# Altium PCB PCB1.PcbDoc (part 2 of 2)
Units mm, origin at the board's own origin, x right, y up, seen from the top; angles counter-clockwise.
Board outline 98.6 x 67.31 mm, 4 copper layers (Top Layer, GND, PWR, Bottom Layer), stack 1.57 mm thick; 89 components, 101 nets, 372 pads, 350 vias.
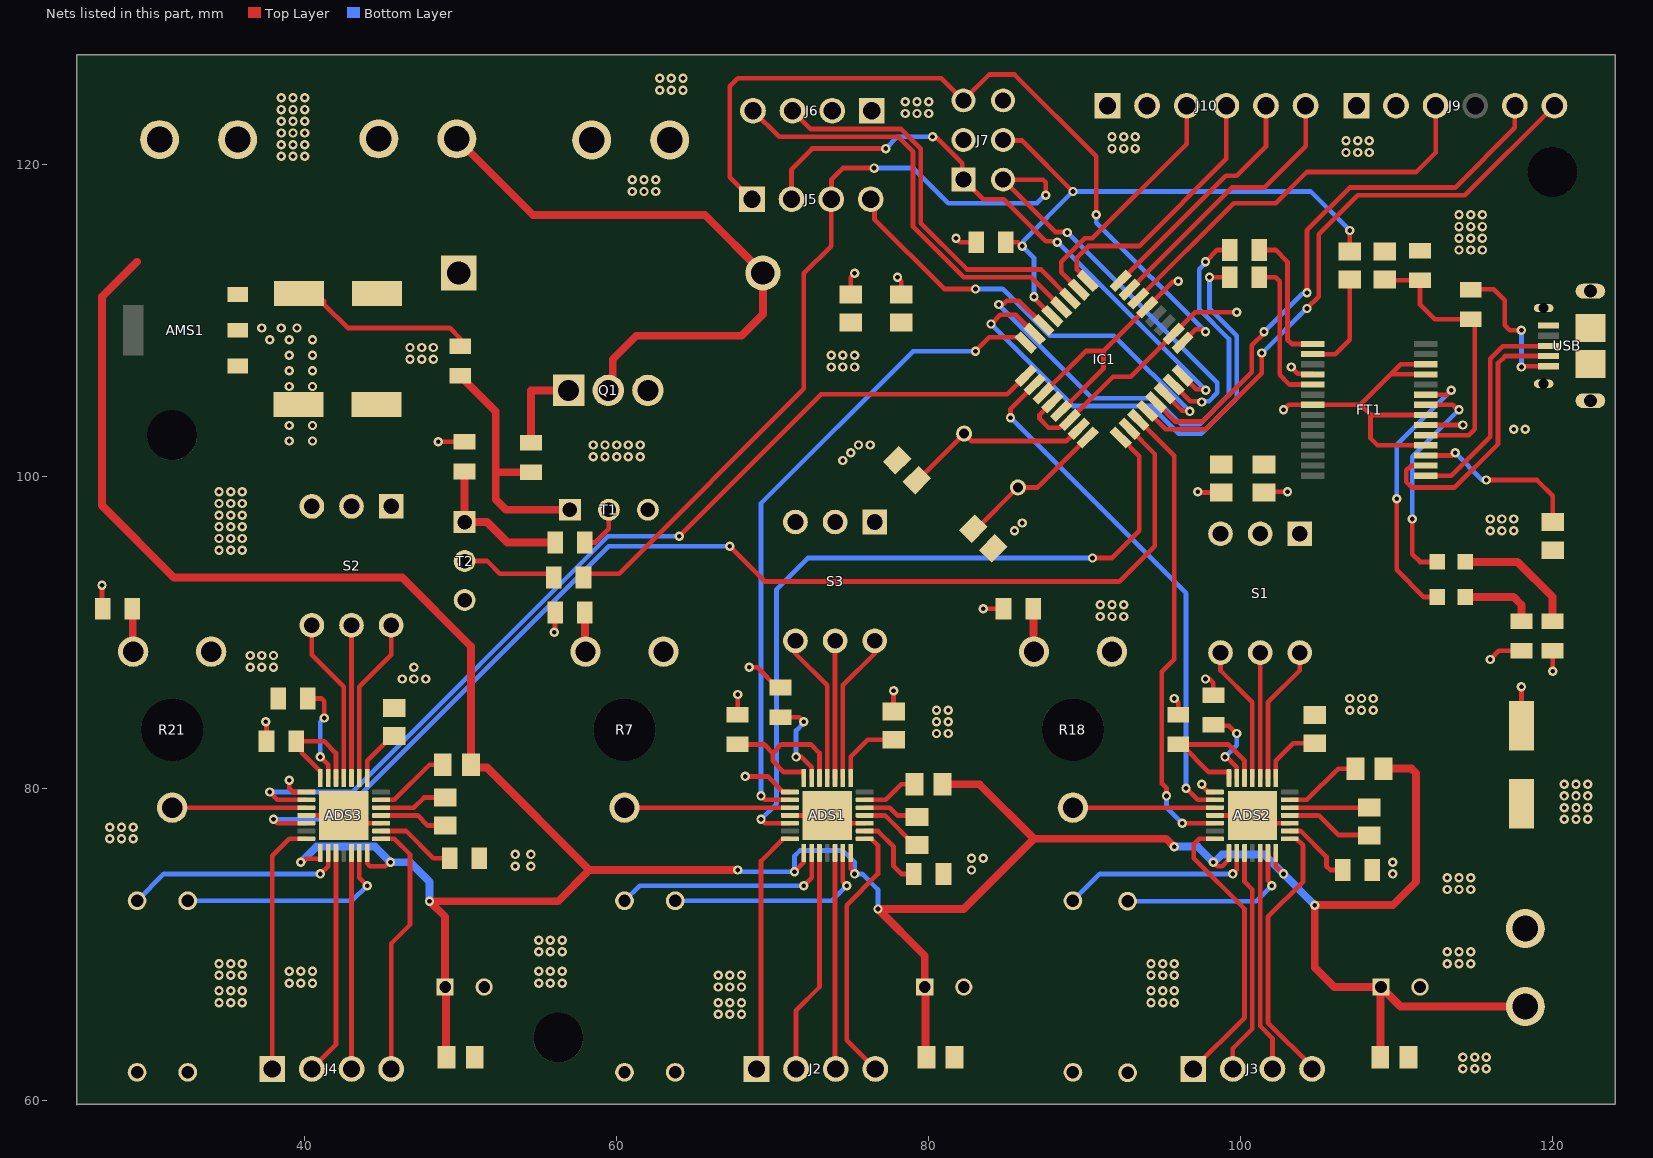
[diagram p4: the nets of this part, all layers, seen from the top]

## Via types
v1: diameter 0.6, hole 0.3, Top Layer to Bottom Layer, 350 vias

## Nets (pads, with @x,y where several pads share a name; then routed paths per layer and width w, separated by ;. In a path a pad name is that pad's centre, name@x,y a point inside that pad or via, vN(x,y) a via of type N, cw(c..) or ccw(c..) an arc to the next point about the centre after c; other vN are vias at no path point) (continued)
ADC7: IC1.22 J9.3 | length 25.9
  Top Layer w0.3: IC1.22@93.442,111.389 99.553,117.5 102.25,117.5 104.25,119.5 111.25,119.5 112.5,120.75 J9.3@112.5,123.75
AT.MOSI: IC1.15 J5.3 J7.4 R31.1 | length 75.6
  Top Layer w0.3: R31.1@57.75,93.25 58.25,93.75 60.15,93.75 72,105.6 72,113 73.75,114.75 J5.3@73.75,117.75 73.775,117.775 73.775,119.025 74.5,119.75 v1(76.5,119.75) ; v1(87.5,118) 87.5,118.834 87.324,119.01 J7.4@84.77,119.01 88.125,115.655 88.845,115.655 v1(88.875,115.625) ; IC1.15@95.705,105.874 96.771,104.807 97.443,104.807 v1(97.5,104.75)
  Bottom Layer w0.3: v1(76.5,119.75) 79,119.75 81.25,117.5 86.939,117.5 87.439,118 v1(87.5,118) ; v1(88.875,115.625) 98.5,106 98.5,105.337 97.971,104.807 97.557,104.807 v1(97.5,104.75)
GND: ADS1.3 ADS1.18 ADS1.29 ADS2.3 ADS2.18 ADS2.29 ADS3.3 ADS3.18 ADS3.29 AMS1.1 C3.1 C4.1 C5.1 C6.1 C11.2 C12.2 C13.2 C14.1 C15.1 C16.1 C17.1 C18.2 C19.2 C20.2 C21.2 C22.2 C23.1 C24.1 C25.1 C26.1 FT1.7 FT1.18 FT1.21 FT1.25 FT1.26 IC1.3 IC1.5 IC1.21 J1.1 J6.1 J7.6 J8.2 J9.1 J10.1 J11.2 Q1.3 R2.1 R4.1 R5.1 R6.1 R7.1 R10.1 R11.1 R14.1 R15.1 R16.1 R17.1 R18.1 R19.1 R20.1 R21.1 R28.1 T1.E T2.E USB.5 USB.S1 USB.S2 USB.S3 USB.S4 USB.S5 USB.S6 | length 59.2
  Top Layer w0.3: ADS3.18@40.1,78.25 42.25,78.25 42.75,77.75 ADS3.3@44.9,77.75 ; v1(68.5,87.75) 69,87.75 70.3,86.45 R2.1@70.5,86.45 ; ADS1.18@71.1,78.25 73.25,78.25 73.75,77.75 ADS1.3@75.9,77.75 ; C6.1@77.75,84.9 v1(77.75,86.25) ; IC1.3@87.361,105.308 90.074,108.021 91.206,108.021 ; IC1.5@88.492,104.177 91.206,106.89 91.206,108.021 ; v1(96,112.5) 95.684,112.5 IC1.21@94.008,110.823 91.206,108.021 ; v1(97.75,87) 98,87 98.25,86.75 R10.1@98.25,85.95 ; ADS2.18@98.35,78.25 ADS2.29@100.75,78.25 101.25,77.75 ADS2.3@103.15,77.75 ; v1(102.75,104.25) 103.075,104.575 FT1.7@104.625,104.575 107.675,104.575 ; FT1.18@111.875,101.975 108.775,101.975 108.325,102.425 108.325,103.925 ; FT1.21@111.875,103.925 108.325,103.925 ; FT1.25@111.875,106.525 109.625,106.525 ; FT1.26@111.875,107.175 110.275,107.175 109.625,106.525 ; 107.675,104.575 108.325,103.925 ; 107.675,104.575 109.625,106.525
  other v1: 114.25,62 115,62 115.75,62 114.25,62.75 115,62.75 115.75,62.75 66.5,65.5 67.25,65.5 68,65.5 34.5,66.25 35.25,66.25 36,66.25 66.5,66.25 67.25,66.25 68,66.25 94.25,66.25 95,66.25 95.75,66.25 34.5,67 35.25,67 36,67 94.25,67 95,67 95.75,67 66.5,67.25 67.25,67.25 68,67.25 39,67.5 39.75,67.5 40.5,67.5 55,67.5 55.75,67.5 56.5,67.5 34.5,68 35.25,68 36,68 66.5,68 67.25,68 68,68 94.25,68 95,68 95.75,68 39,68.25 39.75,68.25 40.5,68.25 55,68.25 55.75,68.25 56.5,68.25 34.5,68.75 35.25,68.75 36,68.75 94.25,68.75 95,68.75 95.75,68.75 113.25,68.75 114,68.75 114.75,68.75 55,69.5 55.75,69.5 56.5,69.5 113.25,69.5 114,69.5 114.75,69.5 55,70.25 55.75,70.25 56.5,70.25 113.25,73.5 114,73.5 114.75,73.5 113.25,74.25 114,74.25 114.75,74.25 109.75,74.5 82.75,74.75 53.5,75 54.5,75 109.75,75.25 82.75,75.5 83.5,75.5 53.5,75.75 54.5,75.75 27.5,76.75 28.25,76.75 29,76.75 27.5,77.5 28.25,77.5 29,77.5 120.75,78 121.5,78 122.25,78 120.75,78.75 121.5,78.75 122.25,78.75 120.75,79.5 121.5,79.5 122.25,79.5 120.75,80.25 121.5,80.25 122.25,80.25 80.5,83.5 81.25,83.5 80.5,84.25 81.25,84.25 80.5,85 81.25,85 107,85 107.75,85 108.5,85 107,85.75 107.75,85.75 108.5,85.75 46.25,87 47,87 47.75,87 36.5,87.75 37.25,87.75 38,87.75 47,87.75 36.5,88.5 37.25,88.5 38,88.5 91,91 91.75,91 92.5,91 91,91.75 91.75,91.75 92.5,91.75 34.5,95.25 35.25,95.25 36,95.25 34.5,96 35.25,96 36,96 85.5,96.5 116,96.5 116.75,96.5 117.5,96.5 34.5,96.75 35.25,96.75 36,96.75 86,97 116,97.25 116.75,97.25 117.5,97.25 34.5,97.5 35.25,97.5 36,97.5 34.5,98.25 35.25,98.25 36,98.25 34.5,99 35.25,99 36,99 74.5,101 58.5,101.25 59.25,101.25 60,101.25 60.75,101.25 61.5,101.25 75,101.5 58.5,102 59.25,102 60,102 60.75,102 61.5,102 75.5,102 76.25,102 117.5,103 118.25,103 73.75,107 74.5,107 75.25,107 46.75,107.5 47.5,107.5 48.25,107.5 73.75,107.75 74.5,107.75 75.25,107.75 46.75,108.25 47.5,108.25 48.25,108.25 114,114.5 114.75,114.5 115.5,114.5 114,115.25 114.75,115.25 115.5,115.25 114,116 114.75,116 115.5,116 114,116.75 114.75,116.75 115.5,116.75 61,118.25 61.75,118.25 62.5,118.25 61,119 61.75,119 62.5,119 38.5,120.5 39.25,120.5 40,120.5 106.75,120.75 107.5,120.75 108.25,120.75 91.75,121 92.5,121 93.25,121 38.5,121.25 39.25,121.25 40,121.25 106.75,121.5 107.5,121.5 108.25,121.5 91.75,121.75 92.5,121.75 93.25,121.75 38.5,122 39.25,122 40,122 38.5,122.75 39.25,122.75 40,122.75 78.5,123.25 79.25,123.25 80,123.25 38.5,123.5 39.25,123.5 40,123.5 78.5,124 79.25,124 80,124 38.5,124.25 39.25,124.25 40,124.25 62.75,124.75 63.5,124.75 64.25,124.75 62.75,125.5 63.5,125.5 64.25,125.5
MISO: IC1.16 J5.2 J7.1 | length 38.5
  Top Layer w0.3: J5.2@71.21,117.75 71.21,119.685 72.525,121 v1(77.25,121) ; v1(80.25,121.75) 80.307,121.693 80.517,121.693 81.115,121.095 81.115,121.088 81.768,120.435 81.775,120.435 82.161,120.049 82.161,119.079 83.49,117.75 84.819,117.75 87.511,115.057 88.193,115.057 v1(88.25,115) ; IC1.16@96.27,106.439 97.143,105.566 97.696,105.566 v1(97.753,105.509)
  Bottom Layer w0.3: v1(77.25,121) 78,121.75 v1(80.25,121.75) ; v1(88.25,115) 88.262,115 v1(97.753,105.509)
MOT_VCC: D1.1 J8.1 J12.1
MS1: ADS2.9 S1.1B | length 8.9
  Top Layer w0.3: ADS2.9@101.75,80.65 101.75,85.5 103.79,87.54 S1.1B@103.79,88.69
MS2: ADS2.10 S1.2B | length 8
  Top Layer w0.3: ADS2.10@101.25,80.65 S1.2B@101.25,88.69
MS3: ADS2.11 S1.3B | length 8.9
  Top Layer w0.3: S1.3B@98.71,88.69 98.71,87.54 100.75,85.5 ADS2.11@100.75,80.65
MS11: ADS3.9 S2.1B | length 10.6
  Top Layer w0.3: ADS3.9@43.5,80.65 43.5,86.5 45.54,88.54 S2.1B@45.54,90.44
MS22: ADS3.10 S2.2B | length 9.8
  Top Layer w0.3: ADS3.10@43,80.65 43,81.075 S2.2B@43,90.44
MS33: ADS3.11 S2.3B | length 10.6
  Top Layer w0.3: S2.3B@40.46,90.44 40.46,88.54 42.5,86.5 ADS3.11@42.5,80.65
MS111: ADS1.9 S3.1B | length 8.8
  Top Layer w0.3: ADS1.9@74.5,80.65 74.5,86.59 76.54,88.63
MS222: ADS1.10 S3.2B | length 8
  Top Layer w0.3: ADS1.10@74,80.65 74,88.63
MS333: ADS1.11 S3.3B | length 9.6
  Top Layer w0.3: S3.3B@71.46,89.44 71.46,88.63 73.5,86.59 ADS1.11@73.5,80.65
NetADS1_1: ADS1.1 J2.4 | length 16.9
  Top Layer w0.3: ADS1.1@75.9,76.75 76.325,76.75 76.75,76.325 76.75,74.5 74.75,72.5 74.75,63.83 J2.4@76.58,62
NetADS1_2: ADS1.2 R4.2 | length 5
  Top Layer w0.3: ADS1.2@75.9,77.25 76.75,77.25 77.75,76.25 77.75,75 78.25,74.5 R4.2@79.05,74.5
NetADS1_4: ADS1.4 C1.2 | length 4.1
  Top Layer w0.3: ADS1.4@75.9,78.25 77.2,78.25 79.1,76.35 C1.2@79.25,76.35
NetADS1_5: ADS1.5 C1.1 | length 3.6
  Top Layer w0.3: ADS1.5@75.9,78.75 77.5,78.75 78,78.25 79.15,78.25 C1.1@79.25,78.15
NetADS1_6: ADS1.6 C2.1 | length 3.6
  Top Layer w0.3: ADS1.6@75.9,79.25 77.25,79.25 78.25,80.25 C2.1@79.1,80.25
NetADS1_8: ADS1.8 C6.2 | length 4.6
  Top Layer w0.3: ADS1.8@75,80.65 75,82 76.1,83.1 C6.2@77.75,83.1
NetADS1_12: ADS1.12 ADS1.14 R1.1 | length 10.7
  Top Layer w0.3: R1.1@67.75,82.8 69.45,82.8 70,82.25 ; ADS1.14@72,80.65 72,81.03 70.72,81.03 70,81.75 70,82.25 ; ADS1.12@73,80.65 73,82.25 72.45,82.8 70.55,82.8 70,82.25
NetADS1_13: ADS1.13 R2.2 | length 6
  Top Layer w0.3: R2.2@70.5,84.55 71.7,84.55 v1(72,84.25) ; v1(71.5,82) 71.844,82 72.5,81.344 ADS1.13@72.5,80.65
  Bottom Layer w0.3: v1(71.5,82) 71.5,83.689 72,84.189 v1(72,84.25)
NetADS1_17: ADS1.17 R7.3 | length 10.6
  Top Layer w0.3: R7.3@60.5,78.75 ADS1.17@71.1,78.75
NetADS1_21: ADS1.21 J2.1 | length 15.9
  Top Layer w0.3: J2.1@68.96,62 69.25,62.29 69.25,75.325 70.675,76.75 ADS1.21@71.1,76.75
NetADS1_23: ADS1.23 R6.2 | length 14.2
  Top Layer w0.3: v1(72,73.75) 72.5,74.25 ADS1.23@72.5,75.85
  Bottom Layer w0.3: R6.2@60.5,72.778 61.472,73.75 v1(72,73.75)
NetADS1_24: ADS1.24 J2.2 | length 14.5
  Top Layer w0.3: J2.2@71.5,62 71.5,65.75 73,67.25 ADS1.24@73,75.85
NetADS1_26: ADS1.26 J2.3 | length 13.9
  Top Layer w0.3: ADS1.26@74,75.85 74,62.04 J2.3@74.04,62
NetADS1_27: ADS1.27 R5.2 | length 13.6
  Top Layer w0.3: ADS1.27@74.5,75.85 74.5,74 v1(74.75,73.75)
  Bottom Layer w0.3: R5.2@63.75,72.778 73.778,72.778 v1(74.75,73.75)
NetADS2_1: ADS2.1 J3.4 | length 17.5
  Top Layer w0.3: ADS2.1@103.15,76.75 103.575,76.75 104,76.325 104,74 101.75,71.75 101.75,64.957 104.58,62.127 J3.4@104.58,62
NetADS2_2: ADS2.2 R14.2 | length 4.8
  Top Layer w0.3: ADS2.2@103.15,77.25 103.844,77.25 105.5,75.594 105.5,75 105.75,74.75 R14.2@106.55,74.75
NetADS2_4: ADS2.4 C7.2 | length 5.6
  Top Layer w0.3: ADS2.4@103.15,78.25 105,78.25 106.25,77 108.2,77 C7.2@108.25,76.95
NetADS2_5: ADS2.5 C7.1 | length 5.1
  Top Layer w0.3: ADS2.5@103.15,78.75 C7.1@108.25,78.75
NetADS2_6: ADS2.6 C9.1 | length 5
  Top Layer w0.3: ADS2.6@103.15,79.25 104.25,79.25 106.25,81.25 C9.1@107.35,81.25
NetADS2_8: ADS2.8 C14.2 | length 4.1
  Top Layer w0.3: ADS2.8@102.25,80.65 102.25,81.75 103.375,82.875 C14.2@104.75,82.875
NetADS2_12: ADS2.12 ADS2.14 R8.1 | length 9.9
  Top Layer w0.3: R8.1@96,82.8 R8.1@96.2,82.8 ; ADS2.14@99.25,80.65 99.25,81.03 97.97,81.03 R8.1@96.2,82.8 ; ADS2.12@100.25,80.65 100.25,81.75 99.2,82.8 R8.1@96.2,82.8
NetADS2_13: ADS2.13 R10.2 | length 5.3
  Top Layer w0.3: R10.2@98.25,84.05 98.3,84 99.25,84 v1(99.75,83.5) ; v1(99,82) 99.057,81.943 99.151,81.943 99.75,81.344 ADS2.13@99.75,80.65
  Bottom Layer w0.3: v1(99,82) 99.75,82.75 v1(99.75,83.5)
NetADS2_17: ADS2.17 R18.3 | length 9.1
  Top Layer w0.3: R18.3@89.25,78.75 ADS2.17@98.35,78.75
NetADS2_21: ADS2.21 J3.1 | length 18.6
  Top Layer w0.3: J3.1@96.96,62 100.25,65.29 100.25,72.25 97,75.5 97,76.4 97.35,76.75 ADS2.21@98.35,76.75
NetADS2_23: ADS2.23 R17.2 | length 12.4
  Top Layer w0.3: v1(99.5,74.5) 99.75,74.75 ADS2.23@99.75,75.85
  Bottom Layer w0.3: R17.2@89.25,72.778 90.972,74.5 v1(99.5,74.5)
NetADS2_24: ADS2.24 J3.2 | length 14.6
  Top Layer w0.3: J3.2@99.5,62 99.5,63.308 100.75,64.558 100.75,73.5 100.25,74 ADS2.24@100.25,75.85
NetADS2_26: ADS2.26 J3.3 | length 14.2
  Top Layer w0.3: ADS2.26@101.25,75.85 101.25,64.75 102.04,63.96 J3.3@102.04,62
NetADS2_27: ADS2.27 R16.2 | length 11.9
  Top Layer w0.3: ADS2.27@101.75,75.85 101.75,74.081 102,73.831 v1(102,73.75)
  Bottom Layer w0.3: R16.2@92.75,72.75 101,72.75 v1(102,73.75)
NetADS3_1: ADS3.1 J4.4 | length 16.5
  Top Layer w0.3: ADS3.1@44.9,76.75 45.75,76.75 46.75,75.75 46.75,71.25 45.54,70.04 J4.4@45.54,62
NetADS3_2: ADS3.2 R15.2 | length 5.3
  Top Layer w0.3: ADS3.2@44.9,77.25 46.5,77.25 48.25,75.5 R15.2@49.516,75.5
NetADS3_4: ADS3.4 C8.2 | length 4.4
  Top Layer w0.3: ADS3.4@44.9,78.25 47.25,78.25 47.9,77.6 C8.2@49,77.6
NetADS3_5: ADS3.5 C8.1 | length 4.4
  Top Layer w0.3: ADS3.5@44.9,78.75 47,78.75 47.65,79.4 C8.1@49,79.4
NetADS3_6: ADS3.6 C10.1 | length 4.9
  Top Layer w0.3: ADS3.6@44.9,79.25 45.75,79.25 48,81.5 C10.1@48.85,81.5
NetADS3_8: ADS3.8 C15.2 | length 3.5
  Top Layer w0.3: ADS3.8@44,80.65 44,81.75 45.6,83.35 C15.2@45.75,83.35
NetADS3_12: ADS3.12 ADS3.14 R9.1 | length 7.5
  Top Layer w0.3: ADS3.14@41,80.65 41,81.075 39.8,82.275 39.8,82.65 R9.1@39.45,83 41.25,83 42,82.25 ADS3.12@42,80.65
NetADS3_13: ADS3.13 R11.2 | length 6.4
  Top Layer w0.3: R11.2@40.2,85.75 41.074,85.75 41.25,85.574 v1(41.25,84.5) ; v1(41,82) 41.5,81.5 ADS3.13@41.5,80.65
  Bottom Layer w0.3: v1(41,82) 41,84.25 v1(41.25,84.5)
NetADS3_17: ADS3.17 R21.3 | length 8.6
  Top Layer w0.3: R21.3@31.5,78.75 ADS3.17@40.1,78.75
NetADS3_21: ADS3.21 J4.1 | length 16.3
  Top Layer w0.3: J4.1@37.92,62 37.92,75.67 39,76.75 ADS3.21@40.1,76.75
NetADS3_23: ADS3.23 R20.2 | length 14
  Top Layer w0.3: v1(41,74.5) 41.5,75 ADS3.23@41.5,75.85
  Bottom Layer w0.3: R20.2@29.25,72.778 30.972,74.5 v1(41,74.5)
NetADS3_24: ADS3.24 J4.2 | length 14.5
  Top Layer w0.3: J4.2@40.46,62 42,63.54 ADS3.24@42,75.85
NetADS3_26: ADS3.26 J4.3 | length 13.9
  Top Layer w0.3: J4.3@43,62 43,75.425 ADS3.26@43,75.85
NetADS3_27: ADS3.27 R19.2 | length 14.2
  Top Layer w0.3: ADS3.27@43.5,75.85 43.5,74.25 v1(44,73.75)
  Bottom Layer w0.3: R19.2@32.5,72.778 43.028,72.778 v1(44,73.75)
NetC25_2: C25.2 FT1.19 R27.1 R28.2 | length 17.9
  Top Layer w0.3: C25.2@109.25,112.6 109.3,112.55 R28.2@111.5,112.55 111.5,111 112.45,110.05 R27.1@114.75,110.05 115,109.8 115,103 114.625,102.625 FT1.19@111.875,102.625
NetC26_2: C26.2 FT1.17 | length 11
  Top Layer w0.3: FT1.17@111.875,101.325 113.575,101.325 v1(113.75,101.5) ; v1(115.75,99.75) 119,99.75 120,98.75 C26.2@120,97.05
  Bottom Layer w0.3: v1(113.75,101.5) 115.5,99.75 v1(115.75,99.75)
NetC27_1: C27.1 FT1.2 | length 6.6
  Top Layer w0.3: FT1.2@104.625,107.825 106.075,107.825 107,108.75 C27.1@107,112.6
NetD1_2: D1.2 J12.2 Q1.2 | length 38.8
  Top Layer w0.5: J12.2@49.75,121.625 54.625,116.75 65.65,116.75 D1.2@69.375,113.025 69.375,110.375 68,109 61.25,109 59.749,107.499 59.749,105.789 Q1.2@59.46,105.5
NetFT1_15: FT1.15 USB.3 | length 14.3
  Top Layer w0.3: FT1.15@111.875,100.025 113.502,100.025 116,102.523 116,107.516 116.809,108.325 USB.3@119.825,108.325
NetFT1_16: FT1.16 USB.2 | length 18
  Top Layer w0.3: FT1.16@111.875,100.675 110.925,100.675 110.625,100.375 110.625,99.625 110.975,99.275 113.725,99.275 116.5,102.05 116.5,107.25 116.95,107.7 USB.2@119.75,107.7 USB.2@119.825,107.7
NetFT1_22: FT1.22 LED2.1 | length 14.6
  Top Layer w0.3: v1(111,97.25) 111,95 111.5,94.5 LED2.1@112.6,94.5 ; FT1.22@111.875,104.575 113.594,104.575 113.919,104.25 v1(114,104.25)
  Bottom Layer w0.3: v1(111,97.25) 111,101.25 v1(114,104.25)
NetFT1_23: FT1.23 LED1.1 | length 18
  Top Layer w0.3: v1(110,98.552) 110,94 111.75,92.25 LED1.1@112.6,92.25 ; FT1.23@111.875,105.225 113.225,105.225 v1(113.5,105.5)
  Bottom Layer w0.3: v1(110,98.552) 110,102 v1(113.5,105.5)
NetIC1_30: IC1.30 R23.1 | length 33.7
  Top Layer w0.3: v1(84.5,111) 84.557,111.057 84.807,111.057 85,111.25 85.776,111.25 87.334,109.692 IC1.30@87.361,109.692 ; v1(97.75,113.75) 98.5,114.5 R23.1@99.3,114.5
  Bottom Layer w0.3: v1(84.5,111) 90.5,105 94.5,105 96.175,103.325 97.368,103.325 99.25,105.207 99.25,108.793 97.35,110.693 97.35,113.269 97.75,113.669 v1(97.75,113.75)
NetIC1_31: IC1.31 R24.1 | length 32.9
  Top Layer w0.3: v1(84,109.75) 84.6,110.35 85.572,110.35 IC1.31@86.795,109.126 ; v1(98,112.75) R24.1@99.3,112.75
  Bottom Layer w0.3: v1(84,109.75) 89.25,104.5 94.25,104.5 96.025,102.725 97.475,102.725 99.75,105 99.75,109 98,110.75 v1(98,112.75)
NetLED1_2: LED1.2 R25.1 | length 4.9
  Top Layer w0.5: LED1.2@114.4,92.25 117.5,92.25 118,91.75 R25.1@118,90.7
NetLED2_2: LED2.2 R26.1 | length 8.1
  Top Layer w0.5: LED2.2@114.4,94.5 117.75,94.5 120,92.25 R26.1@120,90.7
NetQ1_1: Q1.1 R32.2 | length 5.8
  Top Layer w0.5: R32.2@54.5,102.15 54.5,105.5 Q1.1@56.92,105.5
NetR3_1: R3.1 R7.2 | length 2.8
  Top Layer w0.5: R3.1@57.95,91.5 57.975,91.475 57.975,88.775 R7.2@58,88.75
NetR12_1: R12.1 R18.2 | length 2.8
  Top Layer w0.5: R12.1@86.7,91.5 86.725,91.475 86.725,88.775 R18.2@86.75,88.75
NetR13_1: R13.1 R21.2 | length 2.8
  Top Layer w0.5: R13.1@28.95,91.5 28.975,91.475 28.975,88.775 R21.2@29,88.75
NetR27_2: R27.2 USB.1 | length 9.5
  Top Layer w0.3: R27.2@114.75,111.95 114.775,111.975 116.23,111.975 116.925,111.28 116.925,109.675 117.25,109.35 v1(118,109.35) ; v1@118,107.06 119.075,107.054 119.325,107.053 USB.1@119.75,107.05 USB.1@119.825,107.05
  Bottom Layer w0.3: v1(118,107) v1(118,109.35)
NetR29_1: R29.1 R33.1 T2.C | length 9.6
  Top Layer w0.5: R29.1@50.25,100.3 T2.C@50.25,97.06 51.69,97.06 53,95.75 R33.1@56.05,95.75
NetR30_1: R30.1 R32.1 T1.C | length 16.1
  Top Layer w0.5: R30.1@49.975,106.425 52.25,104.15 52.25,100.25 ; R32.1@54.5,100.25 52.25,100.25 ; T1.C@57,97.845 52.905,97.845 52.25,98.5 52.25,100.25
NetR31_2: R31.2 T2.B | length 6.1
  Top Layer w0.3: T2.B@50.25,94.56 51.69,94.56 52.5,93.75 R31.2@55.97,93.75
NetR33_2: R33.2 T1.B | length 3.1
  Top Layer w0.3: R33.2@57.95,95.75 58.614,95.75 59.5,96.636 T1.B@59.5,97.845
PB0: IC1.12 J9.6 | length 38.3
  Top Layer w0.3: IC1.12@94.008,104.177 95.184,103 97.75,103 101.354,106.604 v1(101.354,107.896) ; v1(104.25,110.75) 105,111.5 105,115.5 107.5,118 114.37,118 J9.6@120.12,123.75
  Bottom Layer w0.3: v1(101.354,107.896) 101.396,107.896 v1(104.25,110.75)
PB1: IC1.13 J9.5 | length 36.1
  Top Layer w0.3: IC1.13@94.573,104.742 95.816,103.5 97.543,103.5 100.704,106.661 100.704,108.378 101.5,109.174 v1(101.5,109.25) ; v1(104.25,111.75) 104.25,115.75 107,118.5 113.75,118.5 117.58,122.33 J9.5@117.58,123.75
  Bottom Layer w0.3: v1(101.5,109.25) 103.943,111.693 104.193,111.693 v1(104.25,111.75)
PC0: IC1.23 J10.6 | length 17.7
  Top Layer w0.3: IC1.23@92.876,111.955 99.422,118.5 101.5,118.5 104.164,121.164 J10.6@104.164,123.75
PC1: IC1.24 J10.5 | length 15.5
  Top Layer w0.3: IC1.24@92.311,112.52 99.04,119.25 99.75,119.25 101.624,121.124 J10.5@101.624,123.75
PC2: IC1.25 J10.4 | length 17.4
  Top Layer w0.3: IC1.25@90.189,112.52 90.189,112.561 89.5,113.25 89.5,114 90.25,114.75 93.5,114.75 99.084,120.334 J10.4@99.084,123.75
PC3: IC1.26 J10.3 | length 15.9
  Top Layer w0.3: IC1.26@89.624,111.955 88.5,113.078 88.5,113.75 90,115.25 90.5,115.25 96.544,121.294 J10.3@96.544,123.75
RESET: C27.2 IC1.29 J7.5 R22.1 | length 37.3
  Top Layer w0.3: J7.5@84.77,121.55 84.805,121.515 85.985,121.515 v1(89.25,118.25) ; R22.1@84.95,115 85.75,115 v1(86,114.75) ; v1(86.75,111.5) 86.75,111.434 IC1.29@87.927,110.258 ; C27.2@107,114.4 v1(107,115.75)
  Bottom Layer w0.3: v1(86.75,111.5) 86.75,114 v1(86,114.75) 86.057,114.807 86.057,115.057 v1(89.25,118.25) 104.5,118.25 v1(107,115.75)
RXD: FT1.5 R24.2 | length 9.8
  Top Layer w0.3: R24.2@101.2,112.75 102.25,112.75 102.5,112.5 102.5,106.5 103.125,105.875 FT1.5@104.625,105.875
SCK: IC1.17 J5.1 J7.3 | length 51
  Top Layer w0.3: J5.1@68.67,117.75 67.25,119.17 67.25,125 67.75,125.5 80.82,125.5 J7.3@82.23,124.09 83.89,125.75 85.5,125.75 90.75,120.5 v1(90.75,116.75) ; IC1.17@96.27,108.561 97.119,109.409 97.51,109.409 97.669,109.25 v1(97.75,109.25)
  Bottom Layer w0.3: v1(90.75,116.75) 90.75,116.25 v1(97.75,109.25)
SCL: IC1.28 J6.4 | length 27.8
  Top Layer w0.3: J6.4@68.735,123.425 70.41,121.75 78.043,121.75 79,120.793 79,116 82.25,112.75 86.566,112.75 IC1.28@88.492,110.823
SDA: IC1.27 J6.3 | length 25.6
  Top Layer w0.3: J6.3@71.275,123.425 72.45,122.25 78.25,122.25 79.5,121 79.5,116.207 82.457,113.25 87.197,113.25 IC1.27@89.058,111.389
SS: IC1.14 J5.4 | length 28.7
  Top Layer w0.3: J5.4@76.29,117.75 76.525,117.515 76.525,116.475 81,112 v1(83,112) ; IC1.14@95.139,105.308 96.24,104.207 96.67,104.207 v1(96.728,104.15)
  Bottom Layer w0.3: v1(83,112) 84.75,112 87.75,109 91.878,109 v1(96.728,104.15)
TXD: FT1.1 R23.2 | length 8.8
  Top Layer w0.3: R23.2@101.2,114.5 102.25,114.5 103,113.75 103,108.75 103.275,108.475 FT1.1@104.625,108.475
VCC_5V: ADS1.15 ADS2.15 ADS3.15 AMS1.2 C16.2 C17.2 C21.1 C22.1 C23.2 C24.2 FT1.4 FT1.20 IC1.4 IC1.6 IC1.18 J6.2 J7.2 J9.2 J10.2 R1.2 R3.2 R8.2 R9.2 R12.2 R13.2 R22.2 R25.2 R26.2 R29.2 S1.1A S1.2A S1.3A S2.1A S2.2A S2.3A S3.1A S3.2A S3.3A | length 50.3
  Top Layer w0.3: v1(27,93) 27,91.55 R13.2@27.05,91.5 ; v1(37.5,84.25) 37.55,84.2 R9.2@37.55,83 ; v1(39,80.5) 39,80 39.25,79.75 ADS3.15@40.1,79.75 ; v1(48.55,102.2) R29.2@50.25,102.2 ; v1(56,90) 56.05,90.05 R3.2@56.05,91.25 R3.2@56.05,91.5 ; R1.2@67.75,84.7 v1(67.75,86) ; v1(68.25,80.75) 69.675,80.75 70.675,79.75 ADS1.15@71.1,79.75 ; C17.2@75,111.65 75,112.75 v1(75.25,113) ; v1(78,112.75) 78.25,112.5 C16.2@78.25,111.65 ; v1(81.75,115.25) 82,115 R22.2@83.05,115 ; v1(83.5,91.5) R12.2@84.8,91.5 ; IC1.4@87.927,104.742 87.109,103.924 87.109,103.676 87.682,103.102 88.372,103.102 88.881,103.611 IC1.6@89.058,103.611 91.816,106.369 92.947,106.369 IC1.18@95.705,109.126 97.078,110.5 v1(99.75,110.5) ; v1(95.75,85.75) 96,85.5 R8.2@96,84.7 ; v1(97.25,99) 97.3,98.95 C23.2@98.75,98.95 ; v1(97.5,80.25) 97.5,80.175 97.925,79.75 ADS2.15@98.35,79.75 ; C24.2@101.5,98.95 101.55,99 v1(103,99) ; v1(103.25,107) 103.675,106.575 104.575,106.575 FT1.4@104.625,106.525 ; FT1.20@111.875,103.275 v1(114.25,103.275) ; v1(116,88.25) 116.55,88.8 R25.2@118,88.8 ; C22.1@118,84 v1(118,86.5) ; v1(120,87.5) R26.2@120,88.8
  other v1: 39,102.25 40.5,102.25 39,103.25 40.5,103.25 39,105.75 40.5,105.75 39,106.75 40.5,106.75 39,107.75 40.5,107.75 37.75,108.75 39,108.75 40.5,108.75 37.25,109.5 38.5,109.5 39.5,109.5
VCC_12V: ADS1.22 ADS1.28 ADS2.22 ADS2.28 ADS3.22 ADS3.28 AMS1.3 C2.2 C3.2 C4.2 C5.2 C9.2 C10.2 C11.1 C12.1 C13.1 C20.1 J1.2 J11.1 R30.2 | length 226.4
  Top Layer w0.3: 40.051,75.47 41,75.47 ADS3.22@41,75.85 ; 41.25,111.25 41.25,111 42.75,109.5 49.3,109.5 49.975,108.825 R30.2@49.975,108.325 ; ADS3.28@44,75.85 44,75.176 44.176,75 45.169,75 45.419,75.25 v1(45.5,75.25) ; v1(71.396,74.646) 72,75.25 ADS1.22@72,75.85 ; ADS1.28@75,75.85 75,74.825 75.25,74.575 v1(75.25,74.5) ; v1(98.25,75.25) 98.5,75 98.825,75 99.25,75.425 ADS2.22@99.25,75.85 ; ADS2.28@102.25,75.85 102.25,75 v1(102.75,74.5)
  Top Layer w0.5: 29.25,113.75 27,111.5 27,98.114 31.614,93.5 46.25,93.5 50.65,89.1 C10.2@50.65,81.5 50.832,81.318 51.682,81.318 58.25,74.75 ; C4.2@49.1,62.75 49.05,62.8 49.05,67.2 C12.1@49,67.25 49,71.75 v1(48,72.75) 56.25,72.75 58.25,74.75 ; v1(67.75,74.75) 58.25,74.75 ; C5.2@79.85,62.75 79.8,62.8 79.8,67.2 C11.1@79.75,67.25 79.75,69.25 v1(76.75,72.25) 82.25,72.25 86.75,76.75 ; C2.2@80.9,80.25 83.25,80.25 86.75,76.75 ; v1(95.75,76.25) 95.723,76.25 95.223,76.75 86.75,76.75 ; C3.2@108.95,62.75 108.975,62.775 108.975,67.225 C13.1@109,67.25 ; C9.2@109.15,81.25 110.957,81.25 111.25,80.957 111.25,74 109.75,72.5 v1(104.75,72.5) 104.75,68.5 106,67.25 C13.1@109,67.25 ; J1.2@118.25,66 110.25,66 C13.1@109,67.25
  Bottom Layer w0.3: v1(67.75,74.75) 67.854,74.646 v1(71.396,74.646) 71.396,75.646 71.75,76 74.5,76 75.25,75.25 v1(75.25,74.5) 75.75,74.5 76.75,73.5 v1(76.75,72.25)
  Bottom Layer w0.5: v1(39.75,75.25) 40.75,76.25 44.5,76.25 v1(45.5,75.25) 46.75,75.25 48,74 v1(48,72.75) ; v1(95.75,76.25) 97.25,76.25 v1(98.25,75.25) 98.311,75.25 98.811,75.75 101.5,75.75 v1(102.75,74.5) v1(104.75,72.5)
X_DIR: ADS1.19 IC1.9 | length 48.4
  Top Layer w0.3: v1(69.25,78) 69.5,77.75 ADS1.19@71.1,77.75 ; v1(90.5,94.75) 91.75,94.75 93.5,96.5 93.5,101.29 IC1.9@92.311,102.48
  Bottom Layer w0.3: v1(69.25,78) 70.25,79 70.25,92.75 72.25,94.75 v1(90.5,94.75)
X_STEP: ADS1.16 IC1.32 | length 42.4
  Top Layer w0.3: v1(69.25,79.5) 69.5,79.25 ADS1.16@71.1,79.25 ; v1@82.872,107.872 83.897,108.897 85.894,108.897 IC1.32@86.23,108.561
  Bottom Layer w0.3: v1(69.25,79.5) 69.25,98.25 79,108 v1(83,108)
XTAL1: C19.1 IC1.7 Y1.1 | length 12.1
  Top Layer w0.3: C19.1@79.25,99.75 79.299,99.75 Y1.1@82.275,102.725 82.75,102.25 88.828,102.25 IC1.7@89.624,103.045
XTAL2: C18.1 IC1.8 Y1.2 | length 9.7
  Top Layer w0.3: C18.1@82.864,96.636 83.087,96.636 Y1.2@85.725,99.275 86.984,99.275 IC1.8@90.189,102.48
Y_DIR: ADS3.19 IC1.10 | length 76
  Top Layer w0.3: v1(38,78) 38.25,77.75 ADS3.19@40.1,77.75 ; v1(67.25,95.5) 69.5,93.25 92.25,93.25 94.5,95.5 94.5,101.422 IC1.10@92.876,103.045
  Bottom Layer w0.3: v1(38,78) 42,78 59.5,95.5 v1(67.25,95.5)
Y_STEP: ADS3.16 IC1.1 | length 62.1
  Top Layer w0.3: v1(37.75,79.75) 38.25,79.25 ADS3.16@40.1,79.25 ; v1(64,96.15) 73.1,105.25 85.04,105.25 IC1.1@86.23,106.439
  Bottom Layer w0.3: v1(37.75,79.75) 43.043,79.75 59.443,96.15 v1(64,96.15)
Z_DIR: ADS2.19 IC1.11 | length 29.8
  Top Layer w0.3: IC1.11@93.442,103.611 95.75,101.303 95.75,88.25 94.95,87.45 94.95,80.3 95.25,80 v1(95.25,79.5) ; v1(96.25,77.75) ADS2.19@98.35,77.75
  Bottom Layer w0.3: v1(95.25,79.5) 95.25,78.75 v1(96.25,77.75)
Z_STEP: ADS2.16 IC1.2 | length 33.3
  Top Layer w0.3: v1(85.25,103.75) 85.25,104.328 IC1.2@86.795,105.874 ; v1(96.5,80) 97.25,79.25 ADS2.16@98.35,79.25
  Bottom Layer w0.3: v1(85.25,103.75) 96.5,92.5 v1(96.5,80)
pads on no net: ADS1.7 ADS1.20 ADS1.25 ADS2.7 ADS2.20 ADS2.25 ADS3.7 ADS3.20 ADS3.25 AMS1.4 FT1.3 FT1.6 FT1.8 FT1.9 FT1.10 FT1.11 FT1.12 FT1.13 FT1.14 FT1.24 FT1.27 FT1.28 IC1.20 R7. R18. R21. USB.4

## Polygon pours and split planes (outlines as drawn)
GND on Bottom Layer "GND_L04_P001" (solid, remove dead copper, pour order 1): 25.5,59.75 25.5,127 124,127 124,59.75
GND on Top Layer "GND_L01_P000" (solid, remove dead copper, pour order 0): 25.5,127 124,127 124,59.75 25.5,59.75
GND on GND (split plane): 123.49,60.231 25.91,60.231 25.91,126.49 123.49,126.49
VCC_5V on PWR (split plane): 123.49,60.231 25.91,60.231 25.91,126.49 123.49,126.49

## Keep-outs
Keep-Out Layer:
  the board outline again, w0.254

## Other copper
Top Layer:
  region net MOT_VCC: 51,110.75 51.25,111 51.25,114.75 47,119 47,123.5 47.75,124.25 55.75,124.25 56.75,123.25 56.75,120 57.25,119.5 59.5,119.5 60.5,120.5 60.5,124.5 59.25,125.75 43.5,125.75 42.75,124.525 42.75,119.5 43.5,118.75 44.25,118.75 48.25,114.75 48.25,111.5 49,110.75 49.3,110.75 50.25,110.75
  region net VCC_12V: 28.5,123 29.5,124 32,124 32.5,123.5 32.5,116.5 36,113 41,113 41.75,112.25 41.75,110.75 41.5,110.5 34.5,110.5 33.5,111.5 30.75,111.5 28.5,113.75
  region net VCC_5V: 34.5,109.75 34.5,108.5 34.75,108.25 37.5,108.25 37.75,108 37.75,102.25 38.5,101.5 40.75,101.5 41.5,102.25 41.5,108.75 40.25,110 34.75,110

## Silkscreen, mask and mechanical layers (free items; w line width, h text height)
Top Overlay:
  text "MOTOR" at 43.75,116.274 h2
  text "MOT PWR" at 58.25,116.274 h2
  text "+" at 30.504,116 h1.52
  text "+" at 56.504,116 h1.52
  text "12V POWER" at 27.5,114.524 h2
  text "12V EXT POWER" at 110.25,76 h2
  text "Y" at 38.997,64.5 h3
  text "X" at 72,64.5 h3
  text "Z" at 99.25,64.25 h3
  text "+" at 118.004,60.5 h1.52
Bottom Overlay:
  text "CNC BOARD" at 84.25,91.56 h5
  text "Miljan Eric" at 56.25,76.944 h5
